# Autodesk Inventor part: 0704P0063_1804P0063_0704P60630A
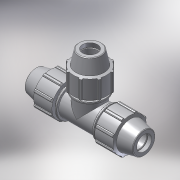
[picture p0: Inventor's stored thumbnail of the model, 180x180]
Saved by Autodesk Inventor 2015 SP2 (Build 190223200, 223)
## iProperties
Created: 2017-02
Part Number: 0704P0063_1804P0063_0704P60630A
Material: PVC-Piping
Description: PLASSON REPAIR TEE 63
Document SubType Name: Modeling
Designer: KIM
Mass: 92.6774 g
Surface Area: 199.44 cm^2
Volume: 66.1981 cm^3
Density: 1.4 g/cm^3
Appearance: Smooth - White
Author: Кирилл
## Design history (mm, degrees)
derived "0704P0.ipt"
feature "Solid1::0704P0.ipt"
tag "TaggingFeature1"
body "Solid1"
other parameters: "d2" = 63, "d4" = 12.16667, "d5" = 36.5, "d7" = 113, "d11" = 4.86667, "d13" = 120 deg, "d14" = 81.9, "d15" = 12 deg, "d16" = 98.31, "d18" = 3.15, "d19" = 35 deg, "d20" = 17.5 deg, "d21" = 105.09, "d23" = 0, "d25" = 360 deg, "d27" = 2.26, "d33" = 1.26, "d42" = 51.1, "d43" = 3.39, "d46" = 1.89, "d67" = 84.75, "d76" = 63, "d77" = 113, "d78" = 12 deg, "d79" = 146, "d80" = 120 deg, "d81" = 81.9, "d82" = 12.16667, "d85" = 84.75, "d86" = 98.31, "d87" = 4.86667, "d88" = 4.86667, "d89" = 36.5, "d90" = 51.1, "d96" = 14.6, "d98" = 105.09, "d99" = 35 deg, "d100" = 17.5 deg, "d102" = 0, "d103" = 2.26, "d107" = 360 deg, "d109" = 1.89, "d112" = 3.15, "d118" = 360 deg, "d121" = 0, "d128" = 294, "d131" = 56.7, "d132" = 56.7, "d134" = 2.2, "d135" = 14.6, "d152" = 0, "d154" = 0, "d156" = 0, "d158" = 0, "d_" = 63, "E_" = 113, "A_" = 146, "H_" = 294
